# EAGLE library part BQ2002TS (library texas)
CHARGE MANAGEMENT IC
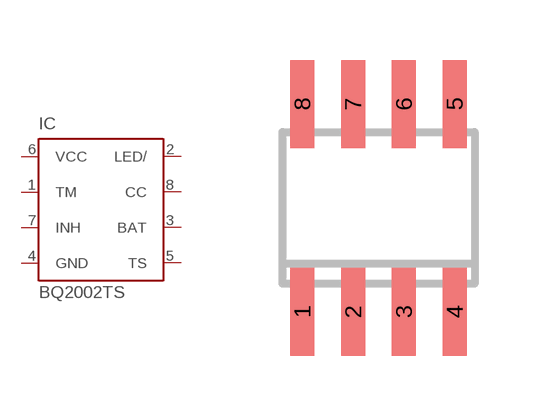
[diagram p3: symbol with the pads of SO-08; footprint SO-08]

Designator prefix IC

## BQ2002TS (MF: TEXAS INSTRUMENTS; MPN: BQ2002TSN; OC_FARNELL: 1564910; OC_NEWARK: 74C7527)  [SO-08]
1  TM  in
2  LED/  oc
3  BAT  in
4  GND  pwr
5  TS  in
6  VCC  pwr
7  INH  in
8  CC  oc

## Footprint SO-08 (pad centres in mm)
D (R-PDSO-G8) Plastic Small Outline Package Source: http://focus.ti.com/lit/ds/symlink/sn65als176.pdf
smd 0.6 x 2.2: 1 -1.905,-2.6; 2 -0.635,-2.6; 3 0.635,-2.6; 4 1.905,-2.6; 5 1.905,2.6; 6 0.635,2.6; 7 -0.635,2.6; 8 -1.905,2.6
